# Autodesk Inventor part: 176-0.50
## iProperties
Created: 2007-07
Part Number: 176-0.50
Document SubType Name: Modeling
Designer: btaylor
Density: 1 g/cm^3
Author: btaylor
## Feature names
1. Extrusion1
2. Mirror1
3. Fillet1
4. Fillet2
5. Extrusion4
6. Chamfer3
7. Chamfer4
